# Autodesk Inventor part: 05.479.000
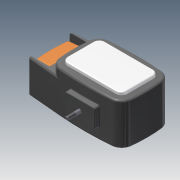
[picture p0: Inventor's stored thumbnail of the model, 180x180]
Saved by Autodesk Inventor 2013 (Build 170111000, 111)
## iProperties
Created: 2005-07
Part Number: 05.479.000
Material: ABS Plastic
Document SubType Name: Modeling
Designer: PVitaliy
Manufacturer: Standard
Standards Organization: Custom
Density: 1 g/cm^3
Author: PVitaliy
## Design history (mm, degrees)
sketch "Эскиз2"
  geometry: L1 (0, 0)-(200, 0); L2 (200, 0)-(200, 140); L3 (200, 140)-(0, 140); L4 (0, 140)-(0, 0); L5 (-150, 70)-(350, 70); L6 (100, 800)-(100, -660); A1 r 800 centre (100, -660) between (200, 133.725) and (0, 133.725); A2 r 800 centre (100, 800) between (0, 6.275) and (200, 6.275); A3 r 350 centre (350, 70) between (5.986, 134.457) and (5.986, 5.543); A4 r 350 centre (-150, 70) between (194.014, 5.543) and (194.014, 134.457); 2 further points
  constraints: 14 point on circle, 12 end point, 6 point on line, 4 centre point, 4 tangent, 2 equal radius, 2 horizontal, 2 parallel, 1 coincident, 1 perpendicular, 1 vertical, 1 other
  dimensions: "d0" = 140 distance of L3.end L1.start; "d1" = 200 distance of L1.start L1.end; "d2" = 800 radius of A1; "d3" = 350 radius of A3
extrude "Выдавливание1" new body sketch "Эскиз2" distance "d4" = 120; taper "d5" = 0 deg
fillet "Сопряжение1" dims "d6" = 30
sketch "Эскиз3"
  geometry: L1 (-29.503, 136.888)-(62, 128.793); L2 (62, 128.793)-(62, 11.207); L3 (-29.503, 3.112)-(62, 11.207); L4 (62, 122.793)-(12, 122.793); L5 (12, 122.793)-(12, 17.207); L6 (12, 17.207)-(62, 17.207); A1 r 30 centre (-32.147, 32.995) between (-29.503, 3.112) and (-2.348, 29.526) reference; A2 r 350 centre (-350, 70) between (-2.348, 29.526) and (-2.348, 110.474) reference; A3 r 30 centre (-32.147, 107.005) between (-2.348, 110.474) and (-29.503, 136.888) reference; A4 r 800 centre (-100, -660) between (-29.503, 136.888) and (-170.497, 136.888) reference; A5 r 350 centre (150, 70) between (-197.652, 110.474) and (-197.652, 29.526) reference; A6 r 800 centre (-100, 800) between (-170.497, 3.112) and (-29.503, 3.112) reference
  constraints: 12 end point, 4 tangent, 2 horizontal, 2 point on line, 2 vertical, 1 point on circle
  dimensions: "d7" = 262 distance edge to line of A5 L2; "d8" = 6 distance from line of L4 L1.end; "d9" = 6 distance from line of L6 L2.end; "d10" = 50 distance between parallel lines of L5 L2
extrude "Выдавливание2" join sketch "Эскиз3" distance "d11" = 90; taper "d12" = 0 deg
sketch "Эскиз4"
  geometry: L1 (90, 0)-(90, 105.586) reference; L2 (0, 105.586)-(90, 105.586) reference; L3 (0, 0)-(0, 105.586) reference; L4 (0, 0)-(90, 0) reference; L5 (8, 101.586)-(82, 101.586); L6 (82, 101.586)-(82, 4); L7 (82, 4)-(8, 4); L8 (8, 4)-(8, 101.586)
  constraints: 8 end point, 2 horizontal, 1 parallel, 1 vertical
  dimensions: "d14" = 4 distance between parallel lines of L5 L2; "d15" = 4 distance between parallel lines of L7 L4; "d16" = 8 distance between parallel lines of L8 L3; "d17" = 8 distance between parallel lines of L1 L6
extrude "Выдавливание3" join sketch "Эскиз4" distance "d18" = 50; taper "d19" = -3 deg
sketch "Эскиз5"
  geometry: L1 (-62, 23.827)-(-62, 116.173) reference; L2 (-12, 118.793)-(-62, 116.173) reference; L3 (-12, 21.207)-(-62, 23.827) reference; L4 (-59, 116.33)-(-59, 23.67); A1 r 359.242 centre (297.242, 70) between (-59, 116.33) and (-59, 23.67); 1 further point
  constraints: 3 point on circle, 2 end point, 2 point on line, 1 centre point, 1 midpoint, 1 tangent, 1 vertical
  dimensions: "d21" = 3 distance between parallel lines of L1 L4
extrude "Выдавливание4" cut sketch "Эскиз5" stored distance "d22" = 50; taper "d23" = 0 deg
sketch "Эскиз6"
  geometry: L1 (20, 120)-(180, 120); L2 (180, 120)-(180, 20); L3 (180, 20)-(20, 20); L4 (20, 20)-(20, 120); A1 r 30 centre (32.147, 32.995) between (2.348, 29.526) and (29.503, 3.112) reference; A2 r 800 centre (100, 800) between (29.503, 3.112) and (170.497, 3.112) reference; A3 r 30 centre (167.853, 32.995) between (170.497, 3.112) and (197.652, 29.526) reference; A4 r 350 centre (-150, 70) between (197.652, 29.526) and (197.652, 110.474) reference; A5 r 30 centre (167.853, 107.005) between (197.652, 110.474) and (170.497, 136.888) reference; A6 r 800 centre (100, -660) between (170.497, 136.888) and (29.503, 136.888) reference; A7 r 30 centre (32.147, 107.005) between (29.503, 136.888) and (2.348, 110.474) reference; A8 r 350 centre (350, 70) between (2.348, 110.474) and (2.348, 29.526) reference
  constraints: 8 end point, 2 parallel, 1 horizontal, 1 perpendicular
  dimensions: "d24" = 20 distance edge to line of A6 L1; "d25" = 20 distance edge to line of A2 L3 (= d24); "d26" = 20 distance edge to line of A4 L2 (= d24); "d27" = 20 distance edge to line of A8 L4 (= d24)
extrude "Выдавливание5" cut sketch "Эскиз6" distance "d28" = 8; taper "d29" = 0 deg
node "РабПлоскость1"
sketch "Эскиз8"
  geometry: L1 (0, 90)-(0, 112) reference; L2 (-200, 0)-(-200, 112) reference; L3 (0, 112)-(-200, 112); L4 (-100, 112)-(-100, 0); L5 (-170.497, 0)-(-29.503, 0) reference; L6 (-60, 82)-(-140, 82); L7 (-140, 82)-(-140, 30); L8 (-140, 30)-(-60, 30); L9 (-60, 30)-(-60, 82); 1 further point
  constraints: 12 end point, 3 midpoint, 2 horizontal, 2 parallel, 1 perpendicular, 1 point on line, 1 vertical
  dimensions: "d31" = 30 distance between parallel lines of L6 L3; "d32" = 30 distance between parallel lines of L8 L5; "d33" = 80 distance of L6.start L6.end
extrude "Выдавливание6" join sketch "Эскиз8" stored distance "d34" = 8; taper "d35" = 0 deg
sketch "Эскиз9"
  geometry: L1 (60, 82)-(140, 82) reference; L2 (60, 30)-(60, 82) reference; L3 (140, 30)-(60, 30) reference; L4 (140, 82)-(140, 30) reference; L5 (100, 82)-(100, 30); L6 (60, 56)-(140, 56); C1 r 5 at (100, 56)
  constraints: 5 midpoint, 4 end point, 1 centre point
  dimensions: "d36" = 10 diameter of C1
extrude "Выдавливание7" join sketch "Эскиз9" distance "d37" = 35; taper "d38" = 0 deg
fillet "Сопряжение2" dims "d39" = 15, "d40" = 5, "d41" = 3
fillet "Сопряжение3" dims "d42" = 8
fillet "Сопряжение4" dims "d43" = 5
fillet "Сопряжение5" dims "d44" = 2
chamfer "Фаска1" distance "d45" = 1; stored, may be unused: second distance "d46" = 2, angle "d47" = 45 deg
feature "Резьба1" dims "d48" = 20, "d49" = 0
body "Solid1"
other parameters: "d30" = -12.5
